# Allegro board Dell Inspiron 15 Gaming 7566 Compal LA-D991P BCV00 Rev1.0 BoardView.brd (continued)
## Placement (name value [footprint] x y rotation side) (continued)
CV563  0.22U_0201_6.3V6M  [C_0201]  153.12 96.67 180 top
CV564  0.22U_0201_6.3V6M  [C_0201]  151.47 97.05 180 top
CV565  0.22U_0201_6.3V6M  [C_0201]  151.47 97.68 180 top
CV566  0.22U_0201_6.3V6M  [C_0201]  153.12 98.06 180 top
CV567  0.22U_0201_6.3V6M  [C_0201]  153.12 98.7 180 top
CV568  0.1U_0402_10V6K  [C_0402]  156.67 83.3 180 top
CV569  0.1U_0402_10V7K  [C_0402]  172.57 80.54 0 top
CV570  0.1U_0402_10V7K  [C_0402]  172.57 79.65 0 top
CV571  1U_0402_6.3V6K  [C_0402]  171.65 79.62 180 top
CV572  4.7U_0603_6.3V6K  [C_0603]  171.51 76.85 180 top
CV573  0.1U_0402_10V7K  [C_0402]  161.77 84.09 0 top
CV574  1U_0402_6.3V6K  [C_0402]  161.77 83.2 0 top
CV575  4.7U_0603_6.3V6K  [C_0603]  160.07 83.22 270 top
CV576  8.2P_0402_50V8D  [C_0402]  62.8 34.15 0 top
CV577  10U_0603_6.3V6M  [C_0603]  62.68 35.3 0 top
CV578  1U_0603_25V6  [C_0603]  67.13 20.69 180 top
CV579  0.1U_0402_25V6  [C_0402]  62.8 25.01 0 top
CV580  0.1U_0402_10V6K  [C_0402]  52.89 36.36 0 bottom
CV581  0.1U_0402_10V6K  [C_0402]  52.89 37.25 0 bottom
CV582  0.1U_0402_10V6K  [C_0402]  229.83 46.73 180 bottom
CV583  8.2P_0402_50V8D  [C_0402]  229.83 45.71 180 bottom
CV584  10U_0603_6.3V6M  [C_0603]  230.83 46.85 0 bottom
CV585  0.1U_0402_10V6K  [C_0402]  52.89 38.14 0 bottom
CV586  0.1U_0402_10V6K  [C_0402]  52.89 39.03 0 bottom
CV587  0.1U_0402_10V6K  [C_0402]  52.89 39.92 0 bottom
CV588  0.1U_0402_10V6K  [C_0402]  52.89 40.8 0 bottom
CV589  0.1U_0402_10V6K  [C_0402]  52.89 41.82 0 bottom
CV590  0.1U_0402_10V6K  [C_0402]  52.89 42.71 0 bottom
CV591  0.1U_0402_10V6K  [C_0402]  52.89 35.47 0 bottom
CV592  0.1U_0402_10V6K  [C_0402]  52.89 34.58 0 bottom
CV597  10U_0603_6.3V6M  [C_0603]  296.36 67.17 180 bottom
CV598  0.1U_0402_10V6K  [C_0402]  296.38 68.32 180 bottom
CV599  0.1U_0402_25V6  [C_0402]  295.46 62.22 0 bottom
CV600  0.1U_0402_25V6  [C_0402]  295.46 71.62 0 bottom
CV601  0.1U_0402_25V6  [C_0402]  295.46 78.35 0 bottom
CV602  0.1U_0402_10V6K  [C_0402]  173.33 75.73 90 top
CV603  0.1U_0402_10V6K  [C_0402]  151.98 76.44 180 top
CZ4  0.01U_0402_16V7K  [C_0402]  211.97 12.5 180 top
CZ6  0.01U_0402_16V7K  [C_0402]  211.97 13.71 180 top
CZ8  10U_0603_6.3V6M  [C_0603]  208.86 12.37 90 top
CZ9  10U_0603_6.3V6M  [C_0603]  207.65 15.67 270 top
CZ11  1U_0603_10V6K  [C_0603]  218.74 11.8 0 top
CZ12  1U_0603_10V6K  [C_0603]  218.64 13.5 0 top
CZ28  0.1U_0402_10V6K  [C_0402]  131.26 94.79 180 top
CZ41  0.1U_0402_10V6K  [C_0402]  63.99 40.88 180 top
CZ43  0.1U_0402_10V6K  [C_0402]  208.42 50.71 90 bottom
CZ44  1U_0402_6.3V6K  [C_0402]  230.69 45.71 0 bottom
CZ47  0.1U_0402_10V6K  [C_0402]  133.92 96.38 0 top
CZ49  0.1U_0402_10V6K  [C_0402]  69.17 48.5 180 top
CZ57  2200P_0402_25V7K  [C_0402]  70.44 48.47 90 top
CZ86  0.1U_0402_10V7K  [C_0402]  131.51 100.65 270 bottom
CZ88  1U_0402_6.3V6K  [C_0402]  134.25 99.1 90 top
CZ95  2200P_0402_25V7K  [C_0402]  170.99 72.51 0 top
CZ96  1U_0402_6.3V6K  [C_0402]  132.35 99.86 0 top
CZ97  0.1U_0402_25V6  [C_0402]  130.72 99.86 180 top
CZ98  2200P_0402_25V7K  [C_0402]  256.8 25.64 90 top
CZ99  0.1U_0402_10V6K  [C_0402]  259.19 27.7 90 top
CZ102  1U_0402_6.3V6K  [C_0402]  150.24 14.34 0 top
CZ104  1U_0402_6.3V6K  [C_0402]  11.74 22.98 0 top
CZ105  0.1U_0402_10V6K  [C_0402]  14.01 35.47 0 top
CZ106  0.1U_0402_10V6K  [C_0402]  13.98 36.64 0 top
CZ107  47U_0805_6.3V6M  [C_0805]  10.8 20.48 90 bottom
D1  -  [BAT54C-7-F_SOT23-3]  275.24 20.44 270 bottom
D2  -  [BAT54A-7-F_SOT23-3]  272.65 28.44 90 bottom
DA1  -  [TVNST52302AB0_SOT523-3]  271.85 23.04 180 top
DA2  AZ5125-02S.R7G_SOT23-3  [AZ5125-02SPR7G_SOT23-3]  276.62 11.85 0 top
DA3  AZ5125-02S.R7G_SOT23-3  [AZ5125-02SPR7G_SOT23-3]  271.92 11.85 0 top
DA4  AZ5125-02S.R7G_SOT23-3  [AZ5125-02SPR7G_SOT23-3]  293.38 21.99 0 bottom
DA5  AZ5125-02S.R7G_SOT23-3  [AZ5125-02SPR7G_SOT23-3]  294.01 12.16 180 bottom
DA6  -  [AZ5123-01F-R7GR_DFN1006P2X2]  297.11 7.94 45 bottom
DC2  BAT54CW-7-F_SOT323-3~D  [BAT54CW-7-F_SOT323-3]  152.79 20.18 180 bottom
DE4  -  [IP4223CZ6_SO6-6]  147.23 10.49 180 bottom
DE7  -  [RB751S40T1G_SOD523-2]  53.98 32.06 270 top
DE8  AZ5125-01H.R7G_SOD523-2  [AZ5125-01HPR7G_SOD523-2]  238.4 31.36 0 top
DE9  -  [RB751S40T1G_SOD523-2]  244.55 38.09 180 top
DH1  -  [RB751S40T1G_SOD523-2]  168.28 20.75 90 top
DI1  -  [RB751S40T1G_SOD523-2]  63.96 27.93 180 top
DI3  AZ5125-02S.R7G_SOT23-3  [AZ5125-02SPR7G_SOT23-3]  62.09 17.9 90 bottom
DI7  -  [AZ1045-04F_DFN2510P10E-10-9]  293.13 53.19 270 bottom
DI8  AZ5125-02S.R7G_SOT23-3  [AZ5125-02SPR7G_SOT23-3]  290.69 56.89 90 bottom
DI9  -  [AZ1045-04F_DFN2510P10E-10-9]  291.91 34.14 270 bottom
DI10  AZ5125-02S.R7G_SOT23-3  [AZ5125-02SPR7G_SOT23-3]  290.05 37.76 90 bottom
DN1  -  [RB751S40T1G_SOD523-2]  197.37 36.38 270 bottom
DN2  -  [RB751S40T1G_SOD523-2]  196.22 36.38 270 bottom
DV1  -  [RB751S40T1G_SOD523-2]  168.92 14.91 90 bottom
DV2  BAT54CW-7-F_SOT323-3~D  [BAT54CW-7-F_SOT323-3]  65.4 31.46 90 top
DV3  BAT54CW-7-F_SOT323-3~D  [BAT54CW-7-F_SOT323-3]  65.35 33.9 90 top
DV4  -  [AZ1045-04F_DFN2510P10E-10-9]  296.54 78.15 180 top
DV5  -  [AZ1045-04F_DFN2510P10E-10-9]  292.44 66.35 0 top
DV9  -  [RB751S40T1G_SOD523-2]  162.99 73.73 0 bottom
DV11  -  [RB751S40T1G_SOD523-2]  175.07 74.67 180 top
DV12  -  [PESD5V0U2BT_SOT23-3]  234.57 36.99 90 bottom
DV13  BAT54CW-7-F_SOT323-3~D  [BAT54CW-7-F_SOT323-3]  159.71 74.67 90 top
EC5205  6.8P_0402_50V8C  [C_0402]  240.67 36.77 270 bottom
EC5206  6.8P_0402_50V8C  [C_0402]  241.69 36.77 270 bottom
F1  0.5A_13.2V_NANOSMDC050F-13.2-2  [F_NANOSMDC050F-13P2-2]  123.05 16.27 0 top
FD1  FIDUCAL  [FIDUCIAL_C40M80]  289.7 23.36 180 bottom
FD2  FIDUCIAL  [FIDUCIAL_C40M80]  4.45 15.48 0 top
FD3  FIDUCAL  [FIDUCIAL_C40M80]  80.02 122.16 180 bottom
FD4  FIDUCIAL  [FIDUCIAL_C40M80]  292.49 111.88 0 top
H1  -  [H_3P7]  80.49 108.8 0 top
H2  -  [H_3P7]  139.79 104.55 0 top
H3  -  [H_3P7]  80.49 70.4 0 top
H4  -  [H_3P7]  139.79 71 0 top
H5  -  [H_3P2]  196.29 114.15 0 top
H6  -  [H_3P2]  210.69 68.55 0 top
H10  -  [H_2P8]  85.19 128.9 0 top
H11  -  [H_2P8]  194.09 128.9 0 top
H12  -  [H_2P8]  285.89 107.9 0 top
H13  -  [H_2P5]  304.79 119.2 0 top
H17  -  [H_2P8]  65.29 76.9 0 top
H19  -  [H_2P8]  214.14 53.1 0 top
H20  -  [H_3P3]  40.79 41.75 0 top
H23  -  [H_2P5]  57.49 57.4 0 top
H40  -  [H_2P1N]  301.29 41 0 top
H55  -  [H_2P4X2P1N]  15.3 41.01 180 top
H56  -  [H_2P5]  88.64 6.97 0 top
H57  -  [H_3P0]  88.64 8.57 0 top
HDA1  ALC3246-CG-GP  [ALC3246-CG_MQFN48_6X6-S]  278.26 26.95 0 top
HT1  100K +-1% 0402 B25/50 4250K  [R_0402]  108.06 85.74 0 top
JADP10  ACES_50290-00701-001  [ACES_50290-00701-001_7P]  8.94 30.41 90 bottom
JAPS  ACES_50506-01841-P01  [ACES_50506-01841-P01_18P]  173.18 11.55 0 top
JBAT10  ACES_50288-01171-001  [ACES_50288-01171-001_11P-T]  45.19 10.84 180 bottom
JBL1  E-T_6913K-Y04N-00L  [E-T_6913K-Y04N-00L_4P]  121.59 15.83 180 bottom
JCAM1  ACES_87212-14G0  [ACES_87212-14G0_14P]  241.02 43.51 0 bottom
JDEG1  ACES_50506-01041-P01  [ACES_50506-01041-P01_10P]  249.22 34.41 0 bottom
JDIMM1  DEREN_40-42271-26001RHF  [DEREN_40-42271-26001RHF_260P-T]  70.65 40.97 0 bottom
JDIMM2  LOTES_ADDR0070-P009A  [LOTES_ADDR0070-P009A_260P-T]  70.66 28.17 180 bottom
JEDP1  ACES_59003-04006-001  [ACES_59003-04006-001_40P]  62.69 24.01 270 bottom
JFAN1  E-T_3806K-F04N-03R  [E-T_3806K-F04N-03R_4P]  56.51 34.65 180 top
JFAN2  E-T_3806K-F04N-03R  [E-T_3806K-F04N-03R_4P]  246.69 34.43 90 top
JHDD1  ACES_50554-01201-001  [ACES_50554-01201-001_12P-T]  195.67 12.21 180 bottom
JHDMI1  ACON_HMR2E-AK120D  [ACON_HMR2E-AK120D_19P]  301.86 78.17 270 bottom
JHP1  SINGA_2SJ3108-007111F  [SINGA_2SJ3108-007111F_6P]  300.84 18.12 90 bottom
JIO1  ACES_88194-3041  [ACES_88194-3041_30P]  9.9 22.75 270 top
JKB1  ACES_50699-03041-P01  [ACES_50699-03041-P01_30P]  196.92 56.91 270 top
JLAN  SANTA_130452-0E1  [SANTA_130452-0E1_8P]  295.47 107.41 270 bottom
JLED  E-T_6915K-Q04N-00L  [E-T_6915K-Q04N-00L_4P]  245.49 24.95 0 top
JLPDE1  ACES_50506-01041-P01  [ACES_50506-01041-P01_10P]  247.02 32.25 180 bottom
JNGFF1  CONCR_213AAAA32FA  [CONCR_213AAAA32FA_67P]  184.31 21.87 0 bottom
JNGFF2  LOTES_APCI0096-P002A  [LOTES_APCI0096-P002A_75P]  208.62 36.82 270 bottom
JPW  ACES_51601-0040M-P01  [ACES_51601-0040M-P01_4P]  201.1 34.66 180 top
JRTC  ACES_50273-0020N-001  [ACES_50273-0020N-001_2P-T]  154.17 13.67 180 bottom
JSPK1  ACES_50224-00601-001  [ACES_50224-00601-001_6P]  300.41 5.88 0 top
JTP  ACES_51524-0080N-001  [ACES_51524-0080N-001_8P]  139.76 15.65 180 bottom
JUART  CVILU_CI1804M1VRA-NH  [CVILU_CI1804M1VRA-NH_4P]  214.21 61.9 90 bottom
JUSB1  LOTES_AUSB0015-P002A  [LOTES_AUSB0015-P002A_9P]  296.41 27.22 270 bottom
JUSB2  LOTES_AUSB0015-P002A  [LOTES_AUSB0015-P002A_9P]  296.41 47.92 270 bottom
LA1  4.7UH +-20% DFE252012F  [TOKO_DFE252012R-H-1R0M_2P]  257.97 12.94 0 bottom
LA2  4.7UH +-20% DFE252012F  [TOKO_DFE252012R-H-1R0M_2P]  261.3 12.97 0 bottom
LA19  BLM15AX700SN1D_2P  [MURAT_BLM15AX700SN1D_2P]  291.51 18.15 0 bottom
LA20  BLM15AX700SN1D_2P  [MURAT_BLM15AX700SN1D_2P]  297.35 15 180 top
LA21  BLM15AX700SN1D_2P  [MURAT_BLM15AX700SN1D_2P]  291.7 16.27 0 top
LA22  BLM15AX700SN1D_2P  [MURAT_BLM15AX700SN1D_2P]  297.86 12.94 180 bottom
LA23  BLM15PX181SN1D_2P  [MURAT_BLM15PX181SN1D_2P]  271.02 16.63 180 top
LA24  BLM15PX181SN1D_2P  [MURAT_BLM15PX181SN1D_2P]  272.69 16.63 0 top
LA25  BLM15PX181SN1D_2P  [MURAT_BLM15PX181SN1D_2P]  275.85 16.63 180 top
LA26  BLM15PX181SN1D_2P  [MURAT_BLM15PX181SN1D_2P]  277.64 16.63 0 top
LED3  HT-F196BP5_WHITE  [LED_HT-F196BP5_2P]  288.3 57.95 180 bottom
LED4  HT-F196BP5_WHITE  [LED_HT-F196BP5_2P]  208.16 34.14 270 top
LH1  BLM15PX221SN1D_2P  [MURAT_BLM15PX221SN1D_2P]  172.22 22.68 90 top
LH2  BLM15PX221SN1D_2P  [MURAT_BLM15PX221SN1D_2P]  179.76 27.68 180 top
LI1  MCM1012B900F06BP_4P  [INPAQ_MCM1012B900F06BP_4P]  67.69 17.39 180 bottom
LI2  MCM1012B900F06BP_4P  [INPAQ_MCM1012B900F06BP_4P]  287.8 35.81 0 bottom
LI5  MCM1012B900F06BP_4P  [INPAQ_MCM1012B900F06BP_4P]  288.44 54.86 0 bottom
LM1  PBY160808T-301Y-N_2P  [CHILI_PBY160808T-300Y-N_2P]  270.03 30.47 180 bottom
LM2  PBY160808T-301Y-N_2P  [CHILI_PBY160808T-300Y-N_2P]  274.22 38.73 180 bottom
LM3  PBY160808T-301Y-N_2P  [CHILI_PBY160808T-300Y-N_2P]  264.3 29.31 90 bottom
LM4  PBY160808T-301Y-N_2P  [CHILI_PBY160808T-300Y-N_2P]  261.23 40.88 0 bottom
LM5  PBY160808T-301Y-N_2P  [CHILI_PBY160808T-300Y-N_2P]  274.22 36.06 180 bottom
LN1  MCM1012B900F06BP_4P  [INPAQ_MCM1012B900F06BP_4P]  185.24 18.03 90 bottom
LV7  PBY160808T-301Y-N_2P  [CHILI_PBY160808T-300Y-N_2P]  162.13 79.58 270 top
LV8  BLM15PD300SN1D_2P  [MURAT_BLM15PX330SN1D_2P]  163.47 78.98 270 top
LV13  BLM15AX300SN1D  [C_0402]  150.33 104.38 180 bottom
LV22  MCM1012B900F06BP_4P  [INPAQ_MCM1012B900F06BP_4P]  231.41 37.65 0 bottom
LV24  HCM1012GH900BP_4P  [INPAQ_HCM1012GH900BP_4P]  294.65 63.73 270 top
LV25  HCM1012GH900BP_4P  [INPAQ_HCM1012GH900BP_4P]  292.74 63.73 270 top
LV26  HCM1012GH900BP_4P  [INPAQ_HCM1012GH900BP_4P]  296.68 74.66 270 top
LV27  HCM1012GH900BP_4P  [INPAQ_HCM1012GH900BP_4P]  294.77 74.66 270 top
NOREF  -  []  65.29 76.9 0 top
NOREF#2  -  []  133.49 8.63 0 top
NOREF#3  -  []  80.49 70.4 0 top
NOREF#4  -  []  191.48 103.72 0 top
NOREF#5  -  []  285.76 11.48 0 top
NOREF#6  -  []  115.45 8.75 0 top
NOREF#7  -  []  224.52 182.21 0 top
NOREF#8  -  []  214.14 53.1 0 top
NOREF#9  -  []  137.24 171.23 0 top
NOREF#10  -  []  139.79 71 0 top
NOREF#11  -  []  85.19 128.9 0 top
NOREF#12  -  []  304.79 119.2 0 top
NOREF#13  -  []  19.79 7.9 0 top
NOREF#14  -  []  184.01 112.87 0 top
NOREF#15  -  []  57.49 57.4 0 top
NOREF#16  -  []  202.74 11.53 0 top
NOREF#17  -  []  80.49 108.8 0 top
NOREF#18  -  []  139.79 104.55 0 top
NOREF#19  -  []  33.55 -30.49 0 top
NOREF#20  -  []  58.24 171.23 0 top
NOREF#21  -  []  164.55 6.94 0 top
NOREF#22  -  []  85.72 49.17 0 top
NOREF#23  -  []  304.79 119.2 0 top
NOREF#24  -  []  194.09 128.9 0 top
NOREF#25  -  []  124.88 50.21 90 top
NOREF#26  -  []  196.29 114.15 0 top
NOREF#27  -  []  210.69 68.55 0 top
NOREF#28  -  []  285.89 107.9 0 top
NOREF#29  -  []  40.79 41.75 0 top
NOREF#30  -  []  285.89 107.9 0 top
NOREF#31  -  []  132.92 66.79 180 bottom
NOREF#32  -  []  121.41 50.07 180 bottom
NOREF#33  -  []  81.29 49.77 180 bottom
NOREF#34  -  []  172.86 110.67 180 bottom
NOREF#35  -  []  86.23 58.66 180 bottom
PC100  0.1U_0402_25V6  [C_0402]  12.33 41.01 90 top
PC101  0.1U_0402_25V6  [C_0402]  12.66 39.23 180 top
PC102  0.1U_0402_25V6  [C_0402]  14.11 34.74 270 bottom
PC103  1000P_0402_50V7K  [C_0402]  15.88 34.74 270 bottom
PC104  100P_0402_50V8J  [C_0402]  15 34.74 270 bottom
PC105  1000P_0402_50V7K  [C_0402]  16.77 34.74 270 bottom
PC106  100P_0402_50V8J  [C_0402]  16.14 38.47 180 top
PC107  15P_0402_50V8J  [C_0402]  16.16 37.56 180 top
PC108  0.1U_0402_25V6  [C_0402]  14.92 26.28 0 bottom
PC109  100P_0402_50V8J  [C_0402]  39.96 16.88 180 bottom
PC110  0.01UF_0402_25V7K  [C_0402]  39.96 17.77 180 bottom
PC111  1000P_0402_50V7K  [C_0402]  46.92 15.36 0 bottom
PC112  100P_0402_50V8J  [C_0402]  46.92 14.47 0 bottom
PC113  0.22U_0603_25V7K  [C_0603]  207.69 62.22 0 bottom
PC114  0.1U_0402_25V6  [C_0402]  227.97 45.51 90 bottom
PC200  0.1U_0402_25V6  [C_0402]  50.3 42.71 90 bottom
PC202  0.022U_0402_25V7K  [C_0402]  46.24 44.87 90 top
PC203  0.1U_0402_25V6  [C_0402]  50.38 39.87 180 bottom
PC204  0.1U_0402_25V6  [C_0402]  48.83 38.85 0 bottom
PC301  0.1U_0402_25V6  [C_0402]  21.17 33.47 90 top
PC302  0.022U_0603_25V7K  [C_0603]  39.82 18.28 180 top
PC303  2200P_0402_50V7K  [C_0402]  24.04 38.95 0 top
PC304  0.047U_0402_25V7K  [C_0402]  28.71 32.96 270 bottom
PC305  0.1U_0402_25V6  [C_0402]  18.98 26.28 0 bottom
PC306  2200P_0402_50V7K  [C_0402]  18.98 26.28 0 top
PC307  10U_0805_25V6K  [C_0805]  18.72 24.88 0 top
PC308  10U_0805_25V6K  [C_0805]  18.72 24.88 0 bottom
PC309  0.1U_0603_25V7K  [C_0603]  24.27 35.84 0 bottom
PC310  0.1U_0402_25V6  [C_0402]  24.7 34.78 0 bottom
PC311  0.01UF_0402_25V7K  [C_0402]  26.49 34.79 270 bottom
PC312  2.2U_0603_16V6K  [C_0603]  31.12 31.55 90 bottom
PC313  1U_0603_25V6K  [C_0603]  27.57 31.55 90 bottom
PC314  10U_0805_25V5K~D  [C_0805]  43.52 18.07 0 bottom
PC315  680P_0402_50V7K  [C_0402]  23.45 25.64 180 top
PC316  10U_0805_25V5K~D  [C_0805]  43.36 16.25 0 top
PC317  10U_0805_25V5K~D  [C_0805]  43.53 18.07 0 top
PC318  0.1U_0402_25V6  [C_0402]  32.19 35.93 0 top
PC319  0.1U_0402_25V6  [C_0402]  34.05 35.92 90 top
PC320  0.1U_0402_25V6  [C_0402]  33.11 36.82 180 top
PC321  100P_0402_50V8J  [C_0402]  27.82 41.34 90 bottom
PC322  100P_0402_50V8J  [C_0402]  29.6 42.23 270 bottom
PC323  0.01UF_0402_25V7K  [C_0402]  26.9 40.69 180 bottom
PC324  1000P_0402_50V7K  [C_0402]  24.01 37.56 0 top
PC400  4.7U_0603_6.3V6M  [C_0603]  55.57 22.22 0 bottom
PC401  100P_0402_50V8J  [C_0402]  56.27 19.09 90 bottom
PC402  100P_0402_50V8J  [C_0402]  55.69 24.25 0 bottom
PC403  15P_0402_50V8J  [C_0402]  57.92 8.19 270 bottom
PC404  0.1U_0402_25V6  [C_0402]  56.14 8.19 270 bottom
PC405  2200P_0402_50V7K  [C_0402]  47.94 25.39 0 bottom
PC406  2200P_0402_50V7K  [C_0402]  56.32 16.12 0 bottom
PC407  10U_0805_25V6K  [C_0805]  47.42 26.79 0 bottom
PC408  0.1U_0402_25V6  [C_0402]  57.03 8.19 270 bottom
PC409  10U_0805_25V6K  [C_0805]  56.69 14.72 0 bottom
PC410  100U_25V_M  [C_ECST250ADA101MF611]  52.08 13.87 90 bottom
PC411  0.1U_0402_25V6  [C_0402]  52.59 18.23 270 bottom
PC412  0.1U_0402_25V6  [C_0402]  51.83 25.97 270 bottom
PC413  150U_B2_6.3VM_R35M  [C_B2]  78.75 10.64 90 bottom
PC414  150U_B2_6.3VM_R35M  [C_B2]  36.31 31.61 0 bottom
PC415  150U_B2_6.3VM_R35M  [C_B2]  36.33 35.06 270 bottom
PC416  .1U_0402_16V7K  [C_0402]  60.72 9.21 270 bottom
PC417  .1U_0402_16V7K  [C_0402]  50 35.68 180 bottom
PC418  680P_0603_50V7K  [C_0603]  65.86 7.61 180 bottom
PC419  680P_0603_50V7K  [C_0603]  44.9 33.77 0 top
PC420  0.1U_0402_25V6  [C_0402]  49.24 20.44 180 bottom
PC421  4.7U_0603_6.3V6M  [C_0603]  48.52 21.39 90 bottom
PC422  0.1U_0402_25V6  [C_0402]  55.69 26.91 0 bottom
PC423  150U_B2_6.3VM_R35M  [C_B2]  36.31 28.31 0 bottom
PC500  10U_0603_25V6M  [C_0603]  96.4 10.72 90 bottom
PC501  10U_0603_25V6M  [C_0603]  97.67 10.72 90 bottom
PC502  0.1U_0402_25V6  [C_0402]  94.37 10.71 90 bottom
PC503  2200P_0402_25V7K  [C_0402]  95.26 10.71 90 bottom
PC504  680P_0402_50V7K  [C_0402]  109.28 8.14 0 bottom
PC505  .1U_0402_16V7K  [C_0402]  104.48 8.22 0 bottom
PC506  1U_0402_6.3V6K  [C_0402]  103.29 8.42 270 bottom
PC507  2.2U_0402_6.3V6M  [C_0402]  102.4 8.42 270 bottom
PC508  330P_0402_50V7K  [C_0402]  100.57 8.22 180 bottom
PC509  22U_0603_6.3V6M  [C_0603]  107.96 15.14 90 bottom
PC510  22U_0603_6.3V6M  [C_0603]  109.23 15.14 90 bottom
PC511  22U_0603_6.3V6M  [C_0603]  113.07 10.4 270 bottom
PC512  22U_0603_6.3V6M  [C_0603]  111.8 10.4 270 bottom
PC513  22U_0603_6.3V6M  [C_0603]  106.69 15.14 90 bottom
PC514  1U_0402_10V6K  [C_0402]  99.7 14.29 90 bottom
PC515  22U_0603_6.3V6M  [C_0603]  101.46 15.1 90 bottom
PC516  22U_0603_6.3V6M  [C_0603]  102.68 15.1 90 bottom
PC517  0.1U_0402_10V7K  [C_0402]  96.43 13.93 90 bottom
PC518  0.1U_0402_10V7K  [C_0402]  98.74 14.32 90 bottom
PC600  680P_0603_50V7K  [C_0603]  254.84 11.98 180 top
PC601  2200P_0402_50V7K  [C_0402]  249.95 18.53 90 bottom
PC602  0.1U_0402_25V6  [C_0402]  250.83 18.53 90 bottom
PC603  10U_0805_25V6K  [C_0805]  254.54 17.99 270 bottom
PC604  10U_0805_25V6K  [C_0805]  254.54 17.99 270 top
PC605  0.1U_0201_10V6K  [C_0201]  247.91 18.95 270 bottom
PC606  330P_0402_50V7K  [C_0402]  250.94 11.22 90 top
PC607  22U_0603_6.3V6M  [C_0603]  236.86 12.31 270 top
PC608  22U_0603_6.3V6M  [C_0603]  236.86 12.31 270 bottom
PC609  22U_0603_6.3V6M  [C_0603]  236.86 14.98 90 bottom
PC610  22U_0603_6.3V6M  [C_0603]  238.9 14.79 90 top
PC611  2.2U_0402_6.3V6M  [C_0402]  247.91 12.77 270 bottom
PC612  0.1U_0402_25V6  [C_0402]  252.49 12.51 270 bottom
PC613  1U_0402_6.3V6K  [C_0402]  248.8 12.51 270 bottom
PC700  680P_0603_50V7K  [C_0603]  63.01 69.21 90 bottom
PC701  0.1U_0201_10V6K  [C_0201]  70.75 70.26 270 top
PC702  2200P_0402_50V7K  [C_0402]  61.58 70.6 270 top
PC703  10U_0805_25V6K  [C_0805]  66.98 71.11 180 top
PC704  10U_0805_25V6K  [C_0805]  63.83 71.01 270 top
PC705  0.1U_0402_25V6  [C_0402]  62.51 70.6 270 top
PC706  22U_0603_6.3V6M  [C_0603]  72.97 64.89 180 top
PC707  22U_0603_6.3V6M  [C_0603]  72.97 66.16 180 top
PC708  22U_0603_6.3V6M  [C_0603]  72.97 67.43 180 top
PC709  22U_0603_6.3V6M  [C_0603]  72.97 63.62 180 top
PC710  2.2U_0402_6.3V6M  [C_0402]  70.49 66.87 270 top
PC711  0.1U_0402_25V6  [C_0402]  64.53 64.2 270 top
PC712  330P_0402_50V7K  [C_0402]  67.75 64.13 0 top
PC713  1U_0402_6.3V6K  [C_0402]  69.61 64.07 270 top
PC800  680P_0603_50V7K  [C_0603]  228.74 41.77 90 top
PC801  2200P_0402_50V7K  [C_0402]  224.72 48.63 0 bottom
PC802  0.1U_0402_25V6  [C_0402]  224.72 48.63 0 top
PC803  0.1U_0201_10V6K  [C_0201]  220.86 47.91 270 bottom
PC804  10U_0805_25V6K  [C_0805]  224.33 47.23 0 bottom
PC805  10U_0805_25V6K  [C_0805]  224.33 47.23 0 top
PC806  330P_0402_50V7K  [C_0402]  219.75 39.89 0 bottom
PC807  22U_0603_6.3V6M  [C_0603]  213.56 42.54 0 bottom
PC808  22U_0603_6.3V6M  [C_0603]  213.56 41.27 0 bottom
PC809  22U_0603_6.3V6M  [C_0603]  213.56 42.54 0 top
PC810  22U_0603_6.3V6M  [C_0603]  213.56 41.27 0 top
PC811  2.2U_0402_6.3V6M  [C_0402]  220.23 42.61 270 bottom
PC812  0.1U_0402_25V6  [C_0402]  226.37 38.85 0 bottom
PC813  1U_0402_6.3V6K  [C_0402]  220.66 40.78 180 bottom
PC900  0.1U_0402_25V6  [C_0402]  140.31 121.28 180 bottom
PC901  2200P_0402_50V7K  [C_0402]  140.31 121.28 180 top
PC902  10U_0805_25V6K  [C_0805]  140.42 119.88 180 top
PC903  10U_0805_25V6K  [C_0805]  140.42 119.88 180 bottom
PC904  0.1U_0603_25V7K  [C_0603]  142.19 115.94 180 bottom
PC905  1U_0603_6.3V6M  [C_0603]  137.98 114.71 270 bottom
PC906  0.1U_0402_16V7K  [C_0402]  141.03 110.1 0 bottom
PC907  10U_0402_6.3V6M  [C_0402]  147.66 116.96 180 bottom
PC908  470U_D2_2VM_R4.5M  [C_D2]  151.9 114.16 180 bottom
PC909  680P_0402_50V7K  [C_0402]  140.6 124.27 180 top
PC1000  0.1U_0402_25V6  [C_0402]  180.02 55.36 0 bottom
PC1001  0.1U_0603_50V7K  [C_0603]  172.73 60.38 270 bottom
PC1002  10U_0805_25V6K  [C_0805]  159.65 48.29 90 bottom
PC1003  10U_0805_25V6K  [C_0805]  168.75 49.9 180 bottom
PC1004  47P_0402_50V8J  [C_0402]  163.71 48.55 90 bottom
PC1005  0.1U_0402_25V6  [C_0402]  164.6 48.55 90 bottom
PC1006  2200P_0402_50V7K  [C_0402]  165.49 48.55 90 bottom
PC1007  100U_25V_M  [C_ECST250ADA101MF611]  147.58 42.95 90 bottom
PC1008  .01U_0402_16V7K  [C_0402]  180.02 56.25 0 bottom
PC1009  2700P_0402_50V7K  [C_0402]  180.81 58.03 180 bottom
PC1010  4.7U_0603_6.3V6K  [C_0603]  164.14 95.59 0 top
PC1011  4.7U_0603_6.3V6K  [C_0603]  165.54 91.9 180 top
PC1012  4.7U_0603_6.3V6K  [C_0603]  166.62 93.1 0 top
PC1013  4.7U_0603_6.3V6K  [C_0603]  165.54 87.9 180 top
PC1014  4.7U_0603_6.3V6K  [C_0603]  165.54 89.1 180 top
PC1015  4.7U_0603_6.3V6K  [C_0603]  166.62 91.9 0 top
PC1016  4.7U_0603_6.3V6K  [C_0603]  168.96 89.17 0 top
PC1017  4.7U_0603_6.3V6K  [C_0603]  166.62 89.1 0 top
PC1018  4.7U_0603_6.3V6K  [C_0603]  166.57 87.83 0 top
PC1019  4.7U_0603_6.3V6K  [C_0603]  168.98 87.85 0 top
PC1020  0.01UF_0402_25V7K  [C_0402]  176.03 58.97 90 bottom
PC1021  330U_B2_2.5VM_R9M  [C_B2]  183.42 70.35 180 top
PC1022  330U_B2_2.5VM_R9M  [C_B2]  145.55 67.07 270 bottom
PC1023  330U_B2_2.5VM_R9M  [C_B2]  150.48 68.7 0 top
PC1024  330U_B2_2.5VM_R9M  [C_B2]  170.44 67.32 270 bottom
PC1025  4.7U_0603_6.3V6K  [C_0603]  168.03 94.33 180 top
PC1026  4.7U_0603_6.3V6K  [C_0603]  165.54 94.37 180 top
PC1027  4.7U_0603_6.3V6K  [C_0603]  165.54 93.1 180 top
PC1028  4.7U_0603_6.3V6K  [C_0603]  173.03 94.37 180 top
PC1029  4.7U_0603_6.3V6K  [C_0603]  169.04 94.44 0 top
PC1030  47P_0603_50V8J  [C_0603]  164.16 54.47 180 top
PC1031  0.01UF_0402_25V7K  [C_0402]  181.62 53.63 90 top
PC1032  100P_0402_50V8J  [C_0402]  180.05 53.61 270 bottom
PC1033  0.1U_0603_50V7K  [C_0603]  173.11 49.96 90 bottom
PC1034  1U_0402_6.3VAK  [C_0402]  169.52 93.36 0 top
PC1035  1U_0402_6.3VAK  [C_0402]  168.02 95.52 180 top
PC1036  1U_0402_6.3VAK  [C_0402]  171.93 88.12 0 top
PC1037  1U_0402_6.3VAK  [C_0402]  166.36 86.75 0 top
PC1038  1U_0402_6.3VAK  [C_0402]  165.5 86.75 180 top
PC1039  1U_0402_6.3VAK  [C_0402]  171.03 85.42 0 top
PC1040  1U_0402_6.3VAK  [C_0402]  169.08 86.42 180 top
PC1041  1U_0402_6.3VAK  [C_0402]  169.93 86.42 0 top
PC1043  10U_0805_25V6K  [C_0805]  154.61 49.65 0 bottom
PC1044  10U_0805_25V6K  [C_0805]  152.07 45.58 0 bottom
PC1045  2200P_0402_50V7K  [C_0402]  161.05 48.55 90 bottom
PC1046  1U_0402_16V6K  [C_0402]  171.92 54.6 180 bottom
PC1047  47P_0402_50V8J  [C_0402]  162.82 48.55 90 bottom
PC1048  0.1U_0402_25V6  [C_0402]  161.93 48.55 90 bottom
PC1051  4.7U_0603_6.3V6K  [C_0603]  174.68 94.57 270 top
PC1052  4.7U_0603_6.3V6K  [C_0603]  174.68 90.76 90 top
PC1053  4.7U_0805_6.3V6K  [C_0805]  167.15 77.36 180 top
PC1054  4.7U_0805_6.3V6K  [C_0805]  166.71 79.14 0 top
PC1055  4.7U_0805_6.3V6K  [C_0805]  166.71 80.92 0 top
PC1056  47P_0603_50V8J  [C_0603]  142.88 57.46 270 top
PC1057  10U_0603_25V6M  [C_0603]  199.91 61.67 270 bottom
PC1058  10U_0603_25V6M  [C_0603]  195.5 61.52 270 bottom
PC1059  47P_0402_50V8J  [C_0402]  197.62 61.15 270 bottom
PC1060  0.1U_0402_25V6  [C_0402]  196.73 61.15 270 bottom
PC1061  2200P_0402_50V7K  [C_0402]  198.51 61.15 270 bottom
PC1062  22U_0603_6.3V6M  [C_0603]  174.68 88.09 90 top
PC1063  22U_0603_6.3V6M  [C_0603]  169.6 85.49 270 top
PC1064  22U_0603_6.3V6M  [C_0603]  168.52 82.82 0 top
PC1065  22U_0603_6.3V6M  [C_0603]  166.87 82.82 180 top
PC1066  22U_0603_6.3V6M  [C_0603]  166.3 85.44 270 top
PC1067  22U_0603_6.3V6M  [C_0603]  165.11 85.44 270 top
PC1068  22U_0603_6.3V6M  [C_0603]  163.7 85.43 270 top
PC1069  22U_0603_6.3V6M  [C_0603]  171.53 89.42 0 top
PC1070  22U_0603_6.3V6M  [C_0603]  170.36 90.44 180 top
PC1071  22U_0603_6.3V6M  [C_0603]  171.55 90.61 0 top
PC1072  22U_0603_6.3V6M  [C_0603]  171.53 91.83 0 top
PC1073  22U_0603_6.3V6M  [C_0603]  171.52 93.11 0 top
PC1074  22U_0603_6.3V6M  [C_0603]  170.38 91.71 180 top
PC1075  22U_0603_6.3V6M  [C_0603]  166.62 90.63 0 top
PC1076  0.1U_0603_50V7K  [C_0603]  199.69 56.96 0 top
PC1077  15P_0402_50V8J  [C_0402]  171.12 84.17 270 top
PC1078  1U_0402_16V6K  [C_0402]  205.09 58.23 180 top
PC1079  15P_0402_50V8J  [C_0402]  172.9 84.17 270 top
PC1080  15P_0402_50V8J  [C_0402]  172.01 84.17 270 top
PC1081  15P_0402_50V8J  [C_0402]  172.85 85.4 0 top
PC1082  47P_0603_50V8J  [C_0603]  192.99 70.48 0 top
PC1083  330U_B2_2.5VM_R9M  [C_B2]  173.68 67.32 270 bottom
PC1084  330U_B2_2.5VM_R9M  [C_B2]  170.44 64.48 90 bottom
PC1085  330U_B2_2.5VM_R9M  [C_B2]  166.02 69.46 180 top
PC1086  330U_B2_2.5VM_R9M  [C_B2]  173.68 64.48 90 bottom
PC1087  330U_B2_2.5VM_R9M  [C_B2]  145.55 64.1 90 bottom
PC1100  4700P_0402_25V7K  [C_0402]  66.43 83.1 90 bottom
PC1101  0.1U_0402_10V7K  [C_0402]  71.76 80.69 90 bottom
PC1102  1U_0402_16V6K  [C_0402]  71.76 84.01 270 bottom
PC1103  0.22U_0603_25V7K  [C_0603]  73.42 84.38 270 bottom
PC1104  330P_0402_50V7K  [C_0402]  65.67 85 90 bottom
PC1105  1000P_0402_50V7K  [C_0402]  65.72 85.97 0 top
PC1106  47P_0402_50V8J  [C_0402]  65.72 86.86 0 top
PC1107  8200P_0402_25V7K  [C_0402]  64.78 86.85 90 top
PC1108  1000P_0402_50V7K  [C_0402]  63.94 88.76 0 bottom
PC1109  680P_0402_50V7K  [C_0402]  64.7 86.92 0 bottom
PC1110  2200P_0402_50V7K  [C_0402]  76.51 87.11 0 bottom
PC1111  .1U_0402_16V7K  [C_0402]  79.44 85.46 0 bottom
PC1112  4700P_0402_16V7K  [C_0402]  79.44 88.13 0 bottom
PC1113  0.033U_0402_16V7K  [C_0402]  79.44 87.24 0 bottom
PC1114  0.01UF_0402_25V7K  [C_0402]  66.63 89.65 180 bottom
PC1115  220P_0402_50V8J  [C_0402]  81.61 92.01 270 bottom
PC1116  0.01UF_0402_25V7K  [C_0402]  76.64 89.14 0 bottom
PC1117  .1U_0402_16V7K  [C_0402]  63.43 90.54 0 bottom
PC1118  0.068U_0402_16V7K  [C_0402]  66.63 90.54 180 bottom
PC1119  2200P_0402_50V7K  [C_0402]  65.72 88.64 0 top
PC1120  330P_0402_50V7K  [C_0402]  76.59 91.73 90 bottom
PC1121  68P_0402_50V8J  [C_0402]  78.55 91.68 0 bottom
PC1122  470P_0402_50V7K  [C_0402]  78.55 90.67 0 bottom
PC1123  2200P_0402_50V7K  [C_0402]  79.46 93.46 180 bottom
PC1124  .1U_0402_16V7K  [C_0402]  64.35 92.32 180 bottom
PC1125  0.022U_0402_25V7K  [C_0402]  74.81 94.78 90 bottom
PC1126  0.022U_0402_25V7K  [C_0402]  65.72 92.32 0 bottom
PC1127  0.022U_0402_25V7K  [C_0402]  73.92 94.78 90 bottom
PC1128  0.022U_0402_25V7K  [C_0402]  73.03 94.78 90 bottom
PC1129  0.022U_0402_25V7K  [C_0402]  65.72 91.43 0 bottom
PC1130  .1U_0402_16V7K  [C_0402]  76.51 98.54 0 bottom
PC1131  .047U_0402_16V7K  [C_0402]  73.03 96.69 90 bottom
PC1132  0.22U_0402_16V7K  [C_0402]  73.92 96.69 90 bottom
PC1133  2200P_0402_50V7K  [C_0402]  77.23 96.69 90 bottom
PC1134  470P_0402_50V7K  [C_0402]  71.51 97.86 270 top
PC1135  0.01UF_0402_25V7K  [C_0402]  71.51 94.78 90 bottom
PC1136  330P_0402_50V7K  [C_0402]  67.95 94.78 90 bottom
PC1137  68P_0402_50V8J  [C_0402]  69.73 95.8 90 top
PC1138  680P_0402_50V7K  [C_0402]  70.62 96.69 90 bottom
PC1139  8200P_0402_25V7K  [C_0402]  69.73 96.69 90 bottom
PC1200  22U_0603_6.3V6M  [C_0603]  121.74 114.16 180 top
PC1201  22U_0603_6.3V6M  [C_0603]  116.91 114.16 0 top
PC1202  22U_0603_6.3V6M  [C_0603]  116.91 112.89 0 top
PC1203  22U_0603_6.3V6M  [C_0603]  108.47 90.35 90 top
PC1204  22U_0603_6.3V6M  [C_0603]  108.47 88.57 270 top
PC1205  22U_0603_6.3V6M  [C_0603]  112.98 114.54 180 top
PC1207  470U_D2_2VM_R4.5M  [C_D2]  115.62 109.24 180 bottom
PC1208  470U_D2_2VM_R4.5M  [C_D2]  120.46 109.31 0 bottom
PC1220  22U_0603_6.3V6M  [C_0603]  119.4 85.51 180 top
PC1221  1U_0402_6.3V6K  [C_0402]  119.34 83.56 180 top
PC1222  1U_0402_6.3V6K  [C_0402]  116.8 85.36 180 top
PC1223  1U_0402_6.3V6K  [C_0402]  116.67 83.22 0 top
PC1224  1U_0402_6.3V6K  [C_0402]  110.3 87.37 0 top
PC1225  1U_0402_6.3V6K  [C_0402]  113.37 87.37 180 top
PC1226  1U_0402_6.3V6K  [C_0402]  110.42 84.95 0 top
PC1229  .1U_0402_16V7K  [C_0402]  113.24 86.22 180 top
PC1230  .1U_0402_16V7K  [C_0402]  113.24 84.95 180 top
PC1231  .1U_0402_16V7K  [C_0402]  118.26 93.76 0 top
PC1232  .1U_0402_16V7K  [C_0402]  110.64 83.16 0 top
PC1233  .1U_0402_16V7K  [C_0402]  119.47 84.45 180 top
PC1239  .1U_0402_16V7K  [C_0402]  109.92 93.39 180 top
PC1240  .1U_0402_16V7K  [C_0402]  118.26 94.65 0 top
PC1241  .1U_0402_16V7K  [C_0402]  110.42 86.22 0 top
PC1242  .1U_0402_16V7K  [C_0402]  110.83 93.38 0 top
PC1243  .1U_0402_16V7K  [C_0402]  116.82 84.45 0 top
PC1244  .1U_0402_16V7K  [C_0402]  110.83 94.27 0 top
PC1245  .1U_0402_16V7K  [C_0402]  113.4 83.16 180 top
PC1246  .1U_0402_16V7K  [C_0402]  108.99 94.3 0 top
PC1247  .1U_0402_16V7K  [C_0402]  120.22 82.46 180 top
PC1248  .1U_0402_16V7K  [C_0402]  115.49 83.29 180 top
PC1261  22U_0603_6.3V6M  [C_0603]  117.04 86.86 180 top
PC1263  22U_0603_6.3V6M  [C_0603]  107.9 114.8 0 top
PC1264  22U_0603_6.3V6M  [C_0603]  107.9 113.53 0 top
PC1265  22U_0603_6.3V6M  [C_0603]  112.98 113.27 180 top
PC1269  22U_0603_6.3V6M  [C_0603]  114.5 84.32 0 top
PC1271  22U_0603_6.3V6M  [C_0603]  114.56 85.52 90 top
PC1274  22U_0603_6.3V6M  [C_0603]  121.74 112.89 180 top
PC1276  22U_0603_6.3V6M  [C_0603]  119.4 86.86 180 top
PC1300  47U_0805_6.3V6M  [C_0805]  102.3 85.95 180 top
PC1301  470U_D2_2VM_R4.5M  [C_D2]  98.96 109.18 0 bottom
PC1303  47U_0805_6.3V6M  [C_0805]  97.56 85.95 0 top
PC1304  47U_0805_6.3V6M  [C_0805]  96.37 85.98 180 top
PC1305  47U_0805_6.3V6M  [C_0805]  96.34 88.18 180 top
PC1306  47U_0805_6.3V6M  [C_0805]  97.75 90.02 0 top
PC1307  470U_D2_2VM_R4.5M  [C_D2]  99.2 114.39 90 bottom
PC1309  47U_0805_6.3V6M  [C_0805]  93.99 107.94 90 bottom
PC1310  47U_0805_6.3V6M  [C_0805]  97.69 88.11 0 top
PC1311  47U_0805_6.3V6M  [C_0805]  96.4 90 180 top
PC1312  47U_0805_6.3V6M  [C_0805]  95.77 107.98 90 bottom
PC1314  22U_0603_6.3V6M  [C_0603]  97.05 91.6 0 top
PC1320  1U_0402_6.3V6K  [C_0402]  107.09 94.35 0 top
PC1321  1U_0402_6.3V6K  [C_0402]  98.77 93.64 0 top
PC1322  1U_0402_6.3V6K  [C_0402]  98.77 92.68 0 top
PC1323  1U_0402_6.3V6K  [C_0402]  105.94 83.17 0 top
PC1324  1U_0402_6.3V6K  [C_0402]  100.86 92.68 0 top
PC1325  1U_0402_6.3V6K  [C_0402]  100.86 93.64 0 top
PC1326  .1U_0402_16V7K  [C_0402]  104.1 83.17 0 top
PC1327  .1U_0402_16V7K  [C_0402]  96.61 93.64 0 top
PC1328  .1U_0402_16V7K  [C_0402]  107.09 93.27 0 top
PC1329  .1U_0402_16V7K  [C_0402]  103.02 93.7 0 top
PC1330  .1U_0402_16V7K  [C_0402]  105.12 92.68 0 top
PC1331  .1U_0402_16V7K  [C_0402]  103.02 92.68 0 top
PC1332  .1U_0402_16V7K  [C_0402]  102.25 83.24 0 top
PC1333  .1U_0402_16V7K  [C_0402]  100.34 83.24 0 top
PC1334  .1U_0402_16V7K  [C_0402]  96.61 92.68 0 top
PC1335  .1U_0402_16V7K  [C_0402]  94.58 92.75 0 top
PC1338  .1U_0402_16V7K  [C_0402]  105.12 93.7 0 top
PC1339  .1U_0402_16V7K  [C_0402]  94.63 83.24 0 top
PC1340  .1U_0402_16V7K  [C_0402]  96.6 83.17 0 top
PC1341  .1U_0402_16V7K  [C_0402]  94.58 93.7 0 top
PC1342  .1U_0402_16V7K  [C_0402]  98.44 83.24 0 top
PC1348  22U_0603_6.3V6M  [C_0603]  102.01 90.26 180 top
PC1349  22U_0603_6.3V6M  [C_0603]  107.14 90.21 180 top
PC1350  22U_0603_6.3V6M  [C_0603]  103.38 86.21 0 top
PC1351  22U_0603_6.3V6M  [C_0603]  107.14 87.53 180 top
PC1352  22U_0603_6.3V6M  [C_0603]  107.14 88.87 180 top
PC1353  22U_0603_6.3V6M  [C_0603]  103.21 87.54 0 top
PC1354  22U_0603_6.3V6M  [C_0603]  103.21 90.27 0 top
PC1359  22U_0603_6.3V6M  [C_0603]  102.02 88.94 180 top
PC1360  22U_0603_6.3V6M  [C_0603]  103.28 88.87 0 top
PC1361  22U_0603_6.3V6M  [C_0603]  101.98 87.55 180 top
PC1362  22U_0603_6.3V6M  [C_0603]  107.14 86.21 180 top
PC1363  22U_0603_6.3V6M  [C_0603]  104.24 84.35 0 top
PC1366  22U_0603_6.3V6M  [C_0603]  100.91 114.16 0 top
PC1367  22U_0603_6.3V6M  [C_0603]  97.74 115.81 0 top
PC1368  22U_0603_6.3V6M  [C_0603]  84.27 116.7 180 top
PC1369  22U_0603_6.3V6M  [C_0603]  97.74 114.54 0 top
PC1370  22U_0603_6.3V6M  [C_0603]  84.27 115.43 180 top
PC1372  22U_0603_6.3V6M  [C_0603]  101.81 84.37 0 top
PC1373  22U_0603_6.3V6M  [C_0603]  99.4 84.37 0 top
PC1374  22U_0603_6.3V6M  [C_0603]  96.99 84.37 0 top
PC1375  22U_0603_6.3V6M  [C_0603]  104.67 91.54 0 top
PC1376  22U_0603_6.3V6M  [C_0603]  103.55 91.6 180 top
PC1377  22U_0603_6.3V6M  [C_0603]  99.59 91.6 0 top
PC1378  22U_0603_6.3V6M  [C_0603]  94.58 84.37 0 top
PC1379  22U_0603_6.3V6M  [C_0603]  96.04 91.63 180 top
PC1380  22U_0603_6.3V6M  [C_0603]  121.87 102.86 180 bottom
PC1382  47U_0805_6.3V6M  [C_0805]  121.88 90.65 180 top
PC1383  .1U_0402_16V7K  [C_0402]  130.26 108.58 180 bottom
PC1384  .1U_0402_16V7K  [C_0402]  135.19 108.58 0 bottom
PC1385  22U_0603_6.3V6M  [C_0603]  121.83 89.13 180 top
PC1386  22U_0603_6.3V6M  [C_0603]  121.65 93.51 180 top
PC1388  47U_0805_6.3V6M  [C_0805]  130.02 112.77 180 bottom
PC1389  22U_0603_6.3V6M  [C_0603]  121.87 104.13 180 bottom
PC1390  22U_0603_6.3V6M  [C_0603]  121.88 87.79 180 top
PC1391  22U_0603_6.3V6M  [C_0603]  134.95 110.99 0 bottom
PC1393  47U_0805_6.3V6M  [C_0805]  129.7 114.25 90 bottom
PC1394  22U_0603_6.3V6M  [C_0603]  134.95 109.72 0 bottom
PC1395  22U_0603_6.3V6M  [C_0603]  130.25 109.72 180 bottom
PC1396  22U_0603_6.3V6M  [C_0603]  130.25 110.99 180 bottom
PC1397  220U_D7_2VM_R6M  [C_EEFSS0D221R]  111.27 90.59 0 top
PC1400  1U_0402_6.3V6K  [C_0402]  120.98 127.45 270 bottom
PC1401  1U_0402_6.3V6K  [C_0402]  124.09 132.02 270 bottom
PC1402  0.22U_0603_16V7K  [C_0603]  125.23 132.26 270 bottom
PC1403  100U_25V_M  [C_ECST250ADA101MF611]  68.71 121.15 180 bottom
PC1404  10U_0805_25V6K  [C_0805]  129.3 127.84 270 top
PC1405  10U_0805_25V6K  [C_0805]  129.3 127.84 270 bottom
PC1406  0.1U_0402_25V6  [C_0402]  127.64 131.1 90 bottom
PC1407  2200P_0402_50V7K  [C_0402]  127.64 131.1 90 top
PC1408  1.5P_0402_50V8C  [C_0402]  128.53 131.1 90 bottom
PC1409  47P_0603_50V8J  [C_0603]  126.76 122.74 90 top
PC1410  1U_0402_6.3V6K  [C_0402]  110.82 127.45 270 bottom
PC1411  1U_0402_6.3V6K  [C_0402]  113.67 132.02 270 bottom
PC1412  0.22U_0603_16V7K  [C_0603]  114.82 132.26 270 bottom
PC1413  10U_0603_25V6M  [C_0603]  119.44 127.87 270 bottom
PC1414  10U_0603_25V6M  [C_0603]  119.44 127.87 270 top
PC1415  0.1U_0402_25V6  [C_0402]  108.47 130.98 90 top
PC1416  2200P_0402_50V7K  [C_0402]  109.36 130.98 90 top
PC1417  47P_0603_50V8J  [C_0603]  116.6 122.74 90 top
PC1418  1U_0402_6.3V6K  [C_0402]  100.91 127.32 270 bottom
PC1419  0.22U_0603_16V7K  [C_0603]  105.17 132.13 270 bottom
PC1420  1U_0402_6.3V6K  [C_0402]  104.02 131.89 270 bottom
PC1421  10U_0805_25V6K  [C_0805]  109.1 127.71 270 bottom
PC1422  10U_0805_25V6K  [C_0805]  109.1 127.71 270 top
PC1423  0.1U_0402_25V6  [C_0402]  107.58 130.98 90 bottom
PC1424  2200P_0402_50V7K  [C_0402]  107.58 130.98 90 top
PC1425  47P_0603_50V8J  [C_0603]  106.69 122.74 90 top
PC1500  1U_0402_6.3V6K  [C_0402]  90.62 127.32 270 bottom
PC1501  1U_0402_6.3V6K  [C_0402]  93.74 131.89 270 bottom
PC1502  0.22U_0603_16V7K  [C_0603]  94.88 132.13 270 bottom
PC1503  10U_0603_25V6M  [C_0603]  99.02 127.87 270 bottom
PC1504  10U_0603_25V6M  [C_0603]  99.02 127.87 270 top
PC1505  0.1U_0402_25V6  [C_0402]  95.82 127.59 270 top
PC1506  2200P_0402_50V7K  [C_0402]  97.16 127.6 270 top
PC1507  680P_0603_50V7K  [C_0603]  96.17 122.74 90 top
PC1508  1U_0402_6.3V6K  [C_0402]  72.4 107.89 270 bottom
PC1509  1U_0402_6.3V6K  [C_0402]  67.37 111.24 0 bottom
PC1510  0.22U_0603_16V7K  [C_0603]  67.13 112.39 0 bottom
PC1511  10U_0805_25V6K  [C_0805]  71.68 116.58 0 top
PC1512  10U_0805_25V6K  [C_0805]  71.68 116.58 0 bottom
PC1513  0.1U_0402_25V6  [C_0402]  68.54 114.8 180 bottom
PC1514  2200P_0402_50V7K  [C_0402]  68.54 114.8 180 top
PC1515  680P_0603_50V7K  [C_0603]  78.56 117.47 180 top
PC1516  2200P_0402_50V7K  [C_0402]  136.03 125.97 270 top
PC1517  0.1U_0402_25V6  [C_0402]  138.82 125.97 270 top
PC1518  10U_0805_25V6K  [C_0805]  137.42 126.48 270 bottom
PC1519  10U_0805_25V6K  [C_0805]  137.42 126.48 270 top
PC1520  4.7U_0402_6.3V6M  [C_0402]  132.85 130.17 270 bottom
PC1521  680P_0603_50V7K  [C_0603]  136.08 121.97 90 top
PC1522  0.22U_0603_16V7K  [C_0603]  133.99 130.42 270 bottom
PC1523  4.7U_0402_6.3V6M  [C_0402]  130.69 126.23 270 bottom
PC1800  0.1U_0402_16V7K  [C_0402]  145.68 17.34 270 bottom
PC1801  22U_0603_6.3V6M  [C_0603]  144.47 17.33 270 bottom
PC1802  22P_0402_50V8J  [C_0402]  146.11 25.83 0 bottom
PC1803  22U_0603_6.3V6M  [C_0603]  144.79 25.96 180 bottom
PC1804  1U_0402_6.3V6K  [C_0402]  143.39 17.34 270 bottom
PD100  AZ5125-01H.R7G_SOD523-2  [AZ5125-01HPR7G_SOD523-2]  15.24 33.14 180 top
PD101  -  [TVNST52302AB0_SOT523-3]  22.55 14.09 90 bottom
PD102  -  [TVNST52302AB0_SOT523-3]  25.41 16.57 180 bottom
PD300  BAT54CW-7-F SOT-323  [BAT54CW_SOT323-3]  24.17 33.7 90 top
PD401  -  [TVNST52302AB0_SOT523-3]  53.1 28.76 180 bottom
PH1100  470K_0402_5%_ TSM0B474J4702RE  [R_0402]  98.43 122.72 90 bottom
PH1101  10K_0402_5%_B25/50 4250K  [R_0402]  130.69 117.26 90 bottom
PH1102  10K_0402_5%_B25/50 4250K  [R_0402]  87.77 120.44 90 bottom
PH1103  10K_0402_5%_B25/50 4250K  [R_0402]  119.77 113.58 90 bottom
PH1104  470K_0402_5%_ TSM0B474J4702RE  [R_0402]  128.03 122.75 270 bottom
PJ600  -  [JUMP_43X79]  254.9 20.86 270 bottom
PJ601  -  [JUMP_43X118]  234.91 13.17 180 bottom
PJ700  JUMP_43X79  [JUMP_43X79-NPM]  71.39 74.93 225 top
PJ701  -  [JUMP_43X118]  72.65 61.37 270 top
PJ800  -  [JUMP_43X79]  221.46 48.63 0 top
PJ801  -  [JUMP_43X118]  211.63 43.17 180 bottom
PJP15  PAD-OPEN 43X39  [JUMP_43X39]  211.2 15.48 180 top
PJP35  PAD-OPEN 43X39  [JUMP_43X39]  66.02 41.35 180 top
PJP36  PAD-OPEN 43X39  [JUMP_43X39]  218.34 38.03 180 bottom
PJP70  PAD-OPEN 43X39  [JUMP_43X39]  147.77 29.97 180 top
PJP300  -  [JUMP_43X79]  20.37 22.09 180 top
PJP400  -  [JUMP_43X118]  44.04 21.58 0 bottom
PJP401  PAD-OPEN 4X4M  [JUMP_43X118]  78.88 13.54 90 bottom
PJP402  PAD-OPEN 4X4M  [JUMP_43X118]  37.47 32.93 270 top
PJP500  -  [JUMP_43X118]  112.56 14.65 90 bottom
PJP501  -  [JUMP_43X39]  104.11 15.87 0 bottom
PJP900  PAD-OPEN 3X3M  [JUMP_43X79]  140.13 117.08 180 top
PJP901  PAD-OPEN 4X4M  [JUMP_43X118]  150.46 118.1 0 top
PJP902  PAD-OPEN 4X4M  [JUMP_43X118]  150.46 112.77 0 top
PJP1302  PAD-OPEN 43X39  [JUMP_43X39]  170.32 38.29 270 top
PJP1303  PAD-OPEN 43X39  [JUMP_43X39]  178.01 37.58 180 top
PJP1304  -  [JUMP_43X39]  152.79 15.98 90 bottom
PJP1400  -  [JUMP_43X118]  120.28 132.37 270 top
PJP1500  -  [JUMP_43X118]  65.41 120.17 270 top
PJP1501  -  [JUMP_43X118]  135.9 132.2 270 top
PL100  HCB2012KF-121T50_0805  [TAI-T_HCB2012KF-121T50_2P]  14.38 36.03 0 bottom
PL101  HCB2012KF-121T50_0805  [TAI-T_HCB2012KF-121T50_2P]  14.38 37.68 0 bottom
PL102  HCB2012KF-121T50_0805  [TAI-T_HCB2012KF-121T50_2P]  14.38 32.5 0 bottom
PL103  HCB2012KF-121T50_0805  [TAI-T_HCB2012KF-121T50_2P]  14.38 30.85 0 bottom
PL104  HCB2012KF-121T50_0805  [TAI-T_HCB2012KF-121T50_2P]  14.38 29.2 0 bottom
PL105  HCB2012KF-121T50_0805  [TAI-T_HCB2012KF-121T50_2P]  14.38 27.55 0 bottom
PL106  BLM15AG102SN1D_2P  [MURAT_BLM15AG102SN1D_2P]  14.91 32.12 180 top
PL107  HCB2012KF-121T50_0805  [TAI-T_HCB2012KF-121T50_2P]  43.46 14.72 0 bottom
PL108  HCB2012KF-121T50_0805  [TAI-T_HCB2012KF-121T50_2P]  43.46 16.37 0 bottom
PL300  HCB2012KF-121T50_0805  [TAI-T_HCB2012KF-121T50_2P]  20.82 19.29 180 top
PL301  HCB2012KF-121T50_0805  [TAI-T_HCB2012KF-121T50_2P]  20.82 17.64 180 top
PL302  5.6UH_PCMB104T-5R6MS_8A_20%  [CYNTE_PCMB104T-5R6MS_2P]  28.68 21.07 0 bottom
PL400  HCB2012KF-121T50_0805  [TAI-T_HCB2012KF-121T50_2P]  43.59 26.79 0 bottom
PL401  HCB2012KF-121T50_0805  [TAI-T_HCB2012KF-121T50_2P]  43.59 25.14 0 bottom
PL402  3.3UH_PCMB063T-3R3MS_6.5A_20%  [CYNTE_PCMB063T-3R3MS_2P]  74.28 11.93 180 bottom
PL403  1.5UH_PCMC063T-1R5MN_9A_20%  [CYNTE_PCMC063T-1R5MN_2P]  41.67 29.96 90 bottom
PL500  HCB2012KF-121T50_0805  [TAI-T_HCB2012KF-121T50_2P]  94.73 7.58 90 bottom
PL501  1UH_PCMB053T-1R0MS_7A_20%  [CYNTE_PCMB053T-1R0MS_2P]  105.25 11.21 0 bottom
PL600  HCB2012KF-121T50_0805  [TAI-T_HCB2012KF-121T50_2P]  252.1 20.8 270 bottom
PL601  1UH_PCMB063T-1R0MS_12A_20%  [CYNTE_PCMB063T-1R0MS_2P]  245.5 14.47 180 bottom
PL700  HCB2012KF-121T50_0805  [TAI-T_HCB2012KF-121T50_2P]  71.71 75.25 225 top
PL701  1UH_PCMB053T-1R0MS_7A_20%  [CYNTE_PCMB053T-1R0MS_2P]  70.98 71.75 0 bottom
PL800  HCB2012KF-121T50_0805  [TAI-T_HCB2012KF-121T50_2P]  220.12 49.08 0 bottom
PL801  1UH_PCMB053T-1R0MS_7A_20%  [CYNTE_PCMB053T-1R0MS_2P]  218.72 45.84 180 bottom
PL900  HCB2012KF-121T50_0805  [TAI-T_HCB2012KF-121T50_2P]  140.46 118.1 180 bottom
PL901  1UH_PCMB063T-1R0MS_12A_20%  [CYNTE_PCMB063T-1R0MS_2P]  149.17 125.44 270 bottom
PL1000  HCB2012KF-121T50_0805  [TAI-T_HCB2012KF-121T50_2P]  153.55 42.52 270 bottom
PL1001  HCB2012KF-121T50_0805  [TAI-T_HCB2012KF-121T50_2P]  151.9 42.52 270 bottom
PL1002  0.22UH_MMD-10DZ-R22MEX2L_35A_20%  [MAG_MMD-10DZ-R22MEX2L_2P]  163.46 59.65 90 bottom
PL1003  0.22UH_MMD-10DZ-R22MEX2L_35A_20%  [MAG_MMD-10DZ-R22MEX2L_2P]  152.54 59.65 90 bottom
PL1004  0.22UH_MMD-10DZ-R22MEX2L_35A_20%  [MAG_MMD-10DZ-R22MEX2L_2P]  191.93 66.79 180 bottom
PL1400  HCB2012KF-121T50_0805  [TAI-T_HCB2012KF-121T50_2P]  120.15 132.94 270 bottom
PL1401  HCB2012KF-121T50_0805  [TAI-T_HCB2012KF-121T50_2P]  117.61 132.94 270 bottom
PL1402  0.22UH_PCME064T-R22MS0R985_28A_20%  [CYNTE_PCME064T-R22MS0R985_2P]  123.76 121.08 270 bottom
PL1403  0.22UH_PCME064T-R22MS0R985_28A_20%  [CYNTE_PCME064T-R22MS0R985_2P]  114.87 121.13 270 bottom
PL1404  0.22UH_PCME064T-R22MS0R985_28A_20%  [CYNTE_PCME064T-R22MS0R985_2P]  105.22 120.96 270 bottom
PL1500  HCB2012KF-121T50_0805  [TAI-T_HCB2012KF-121T50_2P]  67.07 119.38 270 bottom
PL1501  HCB2012KF-121T50_0805  [TAI-T_HCB2012KF-121T50_2P]  65.11 119.38 270 bottom
PL1502  0.22UH_PCME064T-R22MS0R985_28A_20%  [CYNTE_PCME064T-R22MS0R985_2P]  91.76 121 270 bottom
PL1503  0.22UH_PCME064T-R22MS0R985_28A_20%  [CYNTE_PCME064T-R22MS0R985_2P]  79.15 116.96 0 bottom
PL1504  HCB2012KF-121T50_0805  [TAI-T_HCB2012KF-121T50_2P]  137.17 132.2 270 bottom
PL1505  0.47UH_MMD05CZR47M_12A_20%  [MAG_MMD05CZR47M_4P]  134.12 119.88 270 bottom
PQ100  -  [FDV301N-G_SOT23-3]  14.36 30.37 180 top
PQ101  -  [MMBT3904WH_SOT323-3]  14.4 24.76 270 top
PQ102  -  [AON7409_DFN8-5]  208.15 58.74 90 bottom
PQ103  S TR 2N7002KDW 2N SOT-363-6  [2N7002DW-7-F_SOT363-6]  211.17 64.01 0 bottom
PQ200  S TR 2N7002KDW 2N SOT-363-6  [2N7002DW-7-F_SOT363-6]  49.22 44.2 270 bottom
PQ201  L2N7002WT1G 1N SC-70-3  [SSM3K7002FU_SC70-3]  46.55 45.33 270 bottom
PQ202  L2N7002WT1G 1N SC-70-3  [SSM3K7002FU_SC70-3]  47.19 46.35 90 bottom
PQ203  S TR 2N7002KDW 2N SOT-363-6  [2N7002DW-7-F_SOT363-6]  45.92 38.46 90 bottom
PQ300  L2N7002WT1G 1N SC-70-3  [SSM3K7002FU_SC70-3]  19.52 34.15 180 top
PQ301  -  [AON6426_DFN5X6-8-5]  22.49 36.31 180 bottom
PQ302  -  [AON6426_DFN5X6-8-5]  18.3 34.21 0 bottom
PQ303  -  [AON6426_DFN5X6-8-5]  35.57 19.93 0 top
PQ304  -  [AON6428L_DFN8-5]  25.16 22.72 270 bottom
PQ305  -  [AON7518_DFN8-5]  22.54 24.92 90 bottom
PQ306  -  [AON6426_DFN5X6-8-5]  18.68 36.31 0 top
PQ400  AON7408L_DFN8-5  [AON7518_DFN8-5]  59.42 12.8 270 bottom
PQ401  -  [AON6992_DFN5X6D-8-7]  49.92 28.57 180 bottom
PQ402  AON7506_DFN33-8-5  [AON7518_DFN8-5]  63.23 10.37 180 bottom
PQ403  -  [L2N7002WT1G_SC70-3]  55.38 28 180 bottom
PQ900  -  [AON7518_DFN8-5]  142.29 120.85 0 bottom
PQ901  -  [AON6794_DFN5X6-8-5]  139.46 123.05 90 bottom
PQ1000  -  [AON6992_DFN5X6D-8-7]  168.45 55.49 270 bottom
PQ1001  -  [AON6992_DFN5X6D-8-7]  150.29 49.77 270 bottom
PQ1002  -  [AON6992_DFN5X6D-8-7]  205.24 63.2 180 bottom
PQ1004  -  [AON6992_DFN5X6D-8-7]  154.66 51.68 90 bottom
PQ1005  -  [AON6992_DFN5X6D-8-7]  150.29 55.87 270 bottom
PQ1006  -  [AON6992_DFN5X6D-8-7]  199.53 63.2 180 bottom
PR100  0_0402_5%  [R_0402]  16.77 30.17 270 top
PR101  2.2K_0402_1%  [R_0402]  15.81 26.53 0 top
PR102  0_0402_5%  [R0402_0OHM]  16.77 28.39 270 top
PR103  100K_0402_1%  [R_0402]  12.53 26.53 180 top
PR104  10K_0402_1%  [R_0402]  13.4 26.53 0 top
PR105  15K_0402_1%  [R_0402]  11.69 25.59 270 top
PR106  1M_0402_5%  [R_0402]  207.99 63.29 0 bottom
PR107  680K_0402_1%  [R_0402]  210.02 62.93 270 bottom
PR108  100_0402_1%  [R_0402]  23.5 13.25 90 bottom
PR109  100_0402_1%  [R_0402]  24.39 13.25 90 bottom
PR110  100K_0402_1%  [R_0402]  213.47 63.21 90 bottom
PR111  100_0402_1%  [R_0402]  26.25 13.33 180 bottom
PR112  10K_0402_1%  [R_0402]  25.33 14.21 0 bottom
PR113  0_0402_5%  [R0402_0OHM]  208.06 56.96 0 bottom
PR114  33_0402_5%  [R_0402]  14.03 34.15 0 top
PR115  1M_0402_1%  [R_0402]  210.73 56.96 180 bottom
PR200  10K_0402_1%  [R_0402]  35.06 42.23 270 bottom
PR201  6.49K_0402_1%  [R_0402]  34.17 41.32 90 bottom
PR202  10K_0402_5%  [R_0402]  49.46 41.77 0 bottom
PR203  1M_0402_1%  [R_0402]  47.2 41.77 0 bottom
PR204  100K_0402_1%  [R_0402]  50.3 45.41 270 bottom
PR205  10K_0402_1%  [R_0402]  47.14 42.15 180 top
PR206  160K_0402_1%  [R_0402]  46.24 43.09 90 top
PR207  12.4K_0402_1%  [R_0402]  47.13 43.09 90 top
PR208  10K_0402_1%  [R_0402]  49.46 40.76 0 bottom
PR209  1M_0402_1%  [R_0402]  46.34 40.76 180 bottom
PR210  3.3K_0402_1%  [R_0402]  47.2 40.76 0 bottom
PR211  100K_0402_1%  [R_0402]  50.3 47.18 270 bottom
PR212  200K_0402_1%  [R_0402]  49.74 37.96 180 bottom
PR213  1M_0402_1%  [R_0402]  46.24 43.5 270 bottom
PR214  1M_0402_1%  [R_0402]  44.84 39.18 270 bottom
PR215  0_0402_5%  [R0402_0OHM]  47.25 45.79 270 top
PR216  0_0402_5%  [R0402_0OHM]  48.27 45.79 270 top
PR217  0_0402_5%  [R0402_0OHM]  47.25 47.03 90 top
PR300  3M_0402_5%  [R_0402]  21.17 32.63 270 top
PR301  1M_0402_1%  [R_0402]  22.06 31.71 90 top
PR302  0.01_1206_1%  [R_1206_4P-D]  23.59 29.45 0 bottom
PR303  4.7_0402_5%  [R_0402]  17.69 34.48 0 top
PR304  0_0402_5%  [R0402_0OHM]  24.71 32.98 90 bottom
PR305  0_0402_5%  [R0402_0OHM]  25.6 32.98 90 bottom
PR306  10K_0402_1%  [R_0402]  39.63 17.21 270 top
PR307  10_0402_1%  [R_0402]  38.62 17.21 270 top
PR308  4.12K_0603_1%  [R_0603]  24.75 35.6 0 top
PR309  4.12K_0603_1%  [R_0603]  24.27 37.07 0 bottom
PR310  10_1206_1%  [R_1206]  23.53 30.9 0 top
PR311  2.2_0603_5%  [R_0603]  29.85 31.55 90 bottom
PR312  20K_0402_1%  [R_0402]  34.17 34.08 90 bottom
PR313  8.2K_0402_1%  [R_0402]  33.28 34.99 270 bottom
PR314  0.01_1206_1%  [R_1206_4P-D]  41.67 21.8 270 bottom
PR315  4.7_1206_5%  [R_1206]  24.9 23.04 90 top
PR316  100K_0402_1%  [R_0402]  25.03 39.18 0 bottom
PR317  324K_0402_1%  [R_0402]  25.98 41.58 0 bottom
PR318  120K_0402_5%  [R_0402]  25.94 38.29 180 bottom
PR319  0_0402_5%  [R0402_0OHM]  28.71 42.26 270 bottom
PR320  10K_0402_1%  [R_0402]  33.33 38.98 0 bottom
PR321  0_0402_5%  [R0402_0OHM]  35.95 41.32 90 bottom
PR322  10_0402_1%  [R_0402]  33.21 35.93 0 bottom
PR323  52.3K_0402_1%  [R_0402]  26.9 42.47 180 bottom
PR324  10_0402_1%  [R_0402]  33.21 36.82 0 bottom
PR325  4.7_0402_5%  [R_0402]  24.01 36.67 0 top
PR326  0_0402_5%  [R_0402]  31.51 41.32 90 bottom
PR327  0_0402_5%  [R0402_0OHM]  32.39 41.32 90 bottom
PR328  0_0402_5%  [R0402_0OHM]  33.28 41.32 90 bottom
PR329  0_0402_5%  [R_0402]  30.49 41.32 90 bottom
PR400  0_0402_5%  [R0402_0OHM]  56.6 21.07 180 bottom
PR401  68.1K_0402_1%  [R_0402]  57.16 19.09 90 bottom
PR402  154K_0402_1%  [R_0402]  55.69 25.14 0 bottom
PR403  100K_0402_1%  [R_0402]  58.05 19.09 90 bottom
PR404  100K_0402_1%  [R_0402]  55.69 23.36 0 bottom
PR405  22K_0402_1%  [R_0402]  55.38 17.69 90 bottom
PR406  4.75K_0402_1%  [R_0402]  54.49 25.06 90 bottom
PR407  0_0402_5%  [R0402_0OHM]  54.49 17.69 90 bottom
PR408  0_0402_5%  [R0402_0OHM]  57.24 17.26 180 bottom
PR409  0_0402_5%  [R0402_0OHM]  53.6 25.06 90 bottom
PR410  100K_0402_1%  [R_0402]  57.24 18.15 180 bottom
PR411  200_0402_1%  [R_0402]  52.71 25.06 90 bottom
PR412  2.2_0603_5%  [R_0603]  51.44 16.82 90 bottom
PR413  2.2_0603_5%  [R_0603]  50.68 24.82 90 bottom
PR414  4.7_1206_5%  [R_1206]  65.29 11.61 270 bottom
PR415  4.7_1206_5%  [R_1206]  46.94 32.12 180 top
PR416  0_0402_5%  [R0402_0OHM]  49.16 18.58 90 bottom
PR418  2.2K_0402_5%  [R_0402]  56.6 26.03 180 bottom
PR419  0_0402_5%  [R0402_0OHM]  56.02 32.07 270 bottom
PR500  100K_0402_5%  [R_0402]  96 8.22 270 bottom
PR501  100K_0402_5%  [R_0402]  96.89 8.22 270 bottom
PR502  4.7_0805_5%  [R_0805]  106.58 7.8 0 bottom
PR503  51.1K_0402_1%  [R_0402]  100.57 7.33 180 bottom
PR504  0_0402_5%  [R_0402]  97.77 7.31 90 bottom
PR505  48.7K_0402_1%  [R_0402]  101.48 7.36 90 bottom
PR506  0_0402_5%  [R0402_0OHM]  98.66 8.22 270 bottom
PR507  0_0402_5%  [R0402_0OHM]  94.65 14.85 270 bottom
PR508  1M_0402_1%  [R_0402]  95.54 13.93 90 bottom
PR509  0_0402_5%  [R0402_0OHM]  98.71 17.52 270 bottom
PR510  1M_0402_1%  [R_0402]  97.5 14.34 90 bottom
PR511  0_0402_5%  [R_0402]  99.6 17.52 270 bottom
PR600  4.7_1206_5%  [R_1206]  251.99 13.58 0 top
PR601  0_0402_5%  [R0402_0OHM]  248.8 18.46 90 bottom
PR602  14K_0402_1%  [R_0402]  251.8 11.22 90 top
PR603  0_0402_5%  [R0402_0OHM]  254.26 13.17 270 bottom
PR604  1M_0402_1%  [R_0402]  253.37 12.51 270 bottom
PR605  20K_0402_1%  [R_0402]  249.69 12.51 270 bottom
PR606  0_0402_5%  [R_0402]  251.6 11.6 90 bottom
PR607  0_0402_5%  [R_0402]  250.63 12.51 270 bottom
PR700  4.7_1206_5%  [R_1206]  67 69.08 180 bottom
PR701  0_0402_5%  [R0402_0OHM]  69.15 70.35 0 top
PR702  0_0402_5%  [R0402_0OHM]  62.75 63.29 90 top
PR703  100_0402_1%  [R_0402]  66.43 62.42 270 top
PR704  1M_0402_1%  [R_0402]  63.64 64.2 270 top
PR705  0_0402_5%  [R0402_0OHM]  66.51 60.57 180 top
PR706  36.5K_0402_1%  [R_0402]  67.75 63.24 0 top
PR707  0_0402_5%  [R_0402]  65.47 63.36 0 top
PR708  62K_0402_1%  [R_0402]  68.67 62.35 180 top
PR709  0_0402_5%  [R0402_0OHM]  66.38 64.25 180 top
PR710  0_0402_5%  [R0402_0OHM]  66.51 59.68 180 top
PR711  100_0402_1%  [R_0402]  67.75 61.46 0 top
PR712  0_0402_5%  [R0402_0OHM]  191.17 23.51 0 top
PR800  10K_0402_5%  [R_0402]  230.82 42.92 0 top
PR801  0_0402_5%  [R0402_0OHM]  229.88 43.22 90 top
PR802  4.7_1206_5%  [R_1206]  224.67 42.28 0 top
PR803  0_0402_5%  [R0402_0OHM]  221.75 46.65 90 bottom
PR804  62K_0402_1%  [R_0402]  227.29 37.07 180 bottom
PR805  100K_0402_1%  [R_0402]  221.68 39.41 90 bottom
PR806  62K_0402_1%  [R_0402]  226.53 36.19 180 bottom
PR807  1M_0402_1%  [R_0402]  226.37 37.96 0 bottom
PR808  133K_0402_1%  [R_0402]  222.56 40.33 270 bottom
PR809  0_0402_5%  [R_0402]  224.34 39.41 90 bottom
